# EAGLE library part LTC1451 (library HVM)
LINEAR TECHYNOLOGY 12-BIT DAC VOUT(MAX) = 4.095V, REFOUT (INTERNAL) = 2.048V
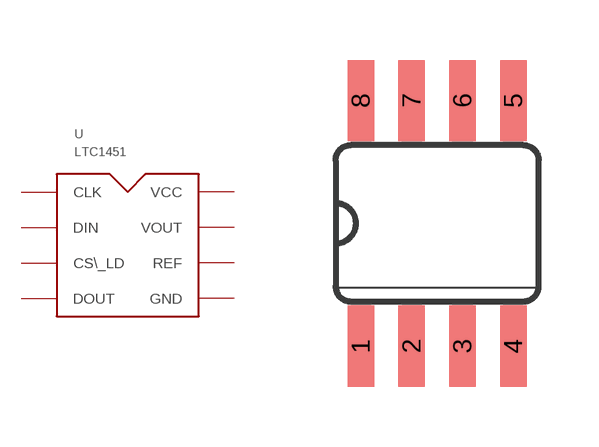
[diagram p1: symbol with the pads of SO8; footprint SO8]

Designator prefix U

## LTC1451  [SO8]
1  CLK  pas
2  DIN  pas
3  CS\_LD  pas
4  DOUT  pas
5  GND  pas
6  REF  pas
7  VOUT  pas
8  VCC  pas

## Footprint SO8 (pad centres in mm)
SO8 PACKAGE
smd 0.66 x 2.032: 1 -1.905,-3.073; 2 -0.635,-3.073; 3 0.635,-3.073; 4 1.905,-3.073; 5 1.905,3.073; 6 0.635,3.073; 7 -0.635,3.073; 8 -1.905,3.073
